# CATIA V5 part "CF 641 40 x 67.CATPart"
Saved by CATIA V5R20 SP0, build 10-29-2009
Part number: CF 641 40 x 67
Definition: NONE
Nomenclature: CF 641 40 x 67
Source: Unknown
Description: CF 641 40 x 67
Bounding box of the stored display mesh (mm): x -37 to 30, y -31.5 to 31.5, z -31.5 to 31.5
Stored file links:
  C:\Users\Utente\Desktop\IO LAVORO\3D X SITO CF\X SITO\CF 641\CF 641 40 x 67.CATPart
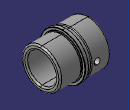
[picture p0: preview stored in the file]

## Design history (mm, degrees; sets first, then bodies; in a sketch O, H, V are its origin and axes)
Body1 "CF 641 40 x 67" (main body)
  Solid1: solid without history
